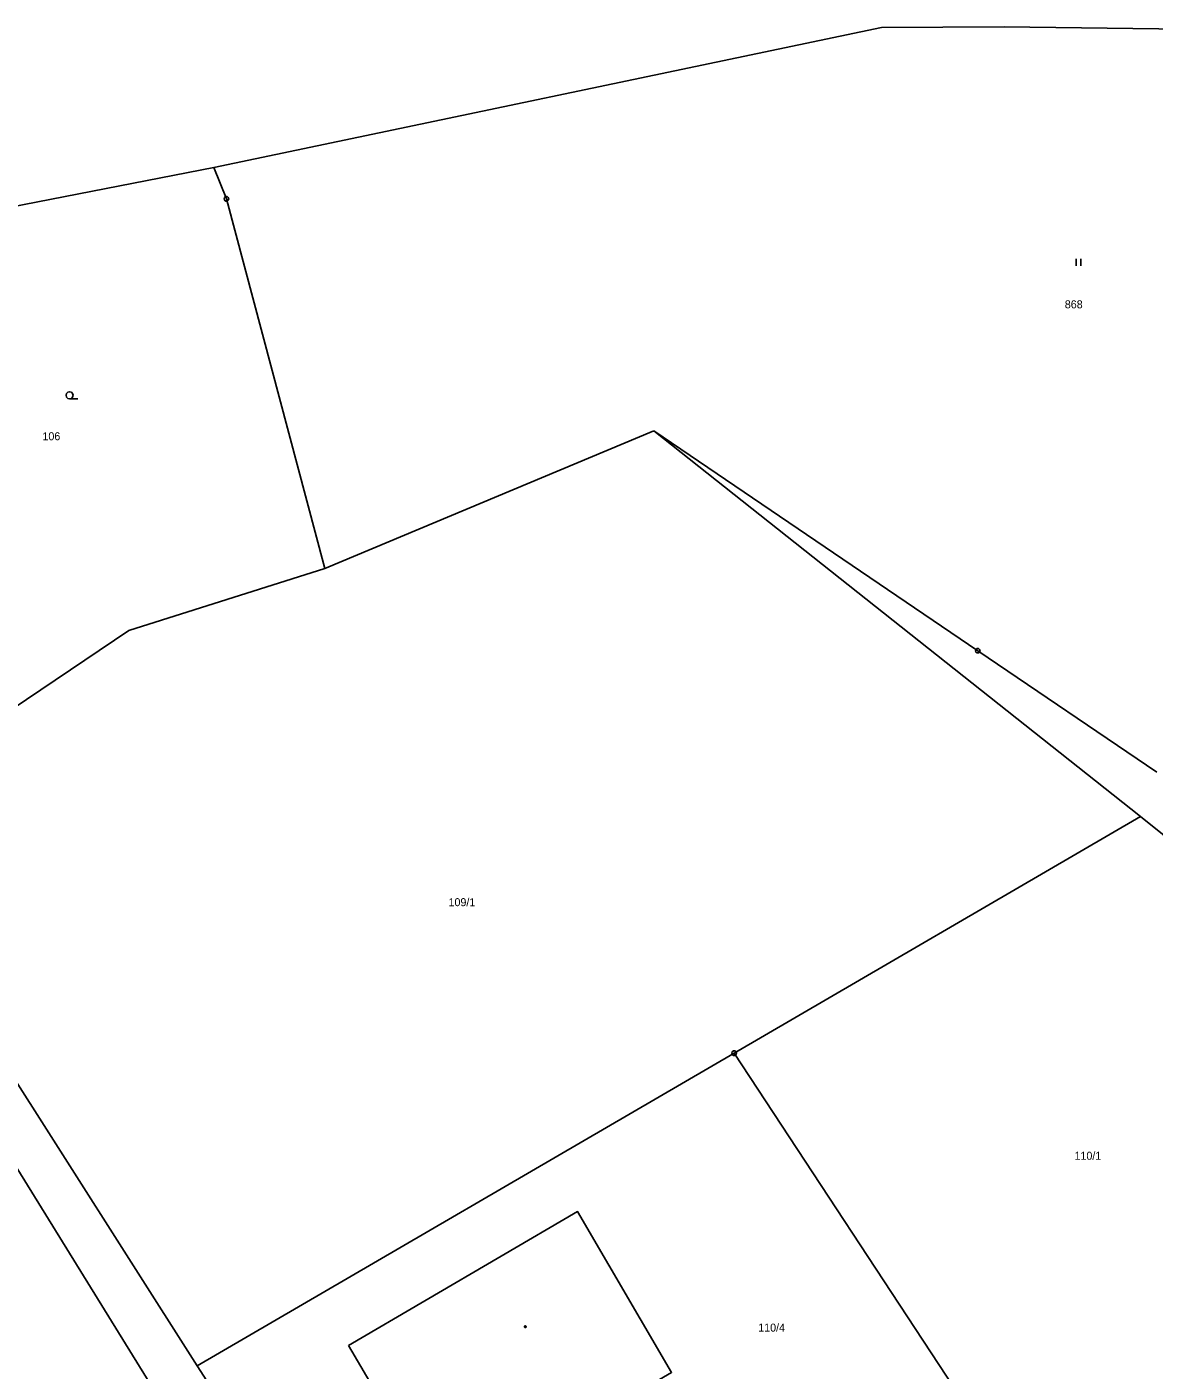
# Model space of a CAD drawing. Extents: x -871430 to -870620, y -1010094 to -1009649.
# Drawn here: x -871056.6 to -870996.8, y -1009793.5 to -1009722.2 of the extents above; entities that cross this region are included whole.
import ezdxf

# ---------------------------------------------------------------- set-up
doc = ezdxf.new("R2010")
doc.units = 0
for name, color, linetype in [('Vrstva 1', 7, 'Continuous'), ('Vrstva 2', 7, 'Continuous'), ('Vrstva 3', 7, 'Continuous'), ('Vrstva 4', 7, 'Continuous'), ('Vrstva 5', 7, 'Continuous'), ('Vrstva 8', 7, 'Continuous')]:
    doc.layers.add(name, color=color, linetype=linetype)

msp = doc.modelspace()

# ---------------------------------------------------------------- linework, layer by layer
at = {"layer": 'Vrstva 1'}
for p, q in [((-871004.72, -1009722.17), (-871011.24, -1009722.21)), ((-870968.56, -1009722.64), (-871004.72, -1009722.17)), ((-871011.24, -1009722.21), (-871046.69, -1009729.64)), ((-871046.69, -1009729.64), (-871080.09, -1009736.13)), ((-871046.69, -1009729.64), (-871046.03, -1009731.31)), ((-871040.81, -1009750.95), (-871046.03, -1009731.31)), ((-871023.32, -1009743.63), (-871040.81, -1009750.95)), ((-871023.32, -1009743.63), (-870997.47, -1009764.12)), ((-871023.32, -1009743.63), (-871006.12, -1009755.31)), ((-871051.22, -1009754.24), (-871040.81, -1009750.95)), ((-871058.73, -1009759.3), (-871051.22, -1009754.24)), ((-871006.12, -1009755.31), (-870996.61, -1009761.77)), ((-871067.43, -1009762.15), (-871047.58, -1009793.3)), ((-871019.06, -1009776.69), (-870997.47, -1009764.12)), ((-870997.47, -1009764.12), (-870970.06, -1009786.29)), ((-871047.58, -1009793.3), (-871019.06, -1009776.69)), ((-871019.06, -1009776.69), (-871005.04, -1009798.01)), ((-871037.49, -1009808.89), (-871047.58, -1009793.3))]:
    msp.add_line(p, q, dxfattribs=at)
msp.add_lwpolyline([(-871039.55, -1009792.22), (-871027.38, -1009785.1), (-871022.38, -1009793.65), (-871034.54, -1009800.76), (-871039.55, -1009792.22)], dxfattribs=at)
at = {"layer": 'Vrstva 3'}
for p, q in [((-871000.895, -1009734.495), (-871000.895, -1009734.87)), ((-871000.645, -1009734.87), (-871000.645, -1009734.495))]:
    msp.add_line(p, q, dxfattribs=at)
msp.add_lwpolyline([(-871054.36, -1009741.93), (-871054.455, -1009741.905), (-871054.522, -1009741.835), (-871054.548, -1009741.742), (-871054.522, -1009741.65), (-871054.455, -1009741.58), (-871054.36, -1009741.555), (-871054.265, -1009741.58), (-871054.198, -1009741.65), (-871054.172, -1009741.742), (-871054.198, -1009741.835), (-871054.265, -1009741.905), (-871054.36, -1009741.93), (-871053.922, -1009741.93)], dxfattribs=at)
at = {"layer": 'Vrstva 4'}
msp.add_line((-871020.6, -1009841.94), (-871072.78, -1009757.54), dxfattribs=at)
at = {"layer": 'Vrstva 5'}
msp.add_lwpolyline([(-871030.15, -1009791.178), (-871030.125, -1009791.182), (-871030.112, -1009791.205), (-871030.108, -1009791.22), (-871030.112, -1009791.242), (-871030.133, -1009791.26), (-871030.15, -1009791.262), (-871030.172, -1009791.255), (-871030.188, -1009791.24), (-871030.192, -1009791.22), (-871030.188, -1009791.198), (-871030.168, -1009791.18), (-871030.15, -1009791.178)], dxfattribs=at)
at = {"layer": 'Vrstva 8'}
for p, q in [((-871046.042, -1009731.31), (-871046.018, -1009731.31)), ((-871006.132, -1009755.31), (-871006.108, -1009755.31)), ((-871019.072, -1009776.69), (-871019.048, -1009776.69))]:
    msp.add_line(p, q, dxfattribs=at)
for points in [[(-871045.992, -1009731.19), (-871045.93, -1009731.238), (-871045.905, -1009731.31), (-871045.93, -1009731.383), (-871045.992, -1009731.43), (-871046.068, -1009731.43), (-871046.13, -1009731.383), (-871046.155, -1009731.31), (-871046.13, -1009731.238), (-871046.068, -1009731.19), (-871045.992, -1009731.19)], [(-871006.082, -1009755.19), (-871006.02, -1009755.238), (-871005.995, -1009755.31), (-871006.02, -1009755.383), (-871006.082, -1009755.43), (-871006.158, -1009755.43), (-871006.22, -1009755.383), (-871006.245, -1009755.31), (-871006.22, -1009755.238), (-871006.158, -1009755.19), (-871006.082, -1009755.19)], [(-871019.023, -1009776.57), (-871018.96, -1009776.617), (-871018.935, -1009776.69), (-871018.96, -1009776.762), (-871019.023, -1009776.81), (-871019.098, -1009776.81), (-871019.16, -1009776.762), (-871019.185, -1009776.69), (-871019.16, -1009776.617), (-871019.098, -1009776.57), (-871019.023, -1009776.57)]]:
    msp.add_lwpolyline(points, dxfattribs=at)

# ---------------------------------------------------------------- texts
at = {"layer": 'Vrstva 2'}
for s, p in [('868', (-871001.497, -1009737.122)), ('106', (-871055.802, -1009744.13)), ('109/1', (-871034.232, -1009768.88)), ('110/1', (-871000.982, -1009782.35)), ('110/4', (-871017.781, -1009791.48))]:
    msp.add_text(s, height=0.425, dxfattribs=at).set_placement(p)

doc.saveas('drawing.dxf')
